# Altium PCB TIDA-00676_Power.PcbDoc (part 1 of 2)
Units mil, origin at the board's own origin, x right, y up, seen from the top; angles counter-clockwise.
Board outline 5000 x 3510 mil, 2 copper layers (Top Layer, Bottom Layer), stack 40 mil thick; 88 components, 29 nets, 205 pads, 45 vias.
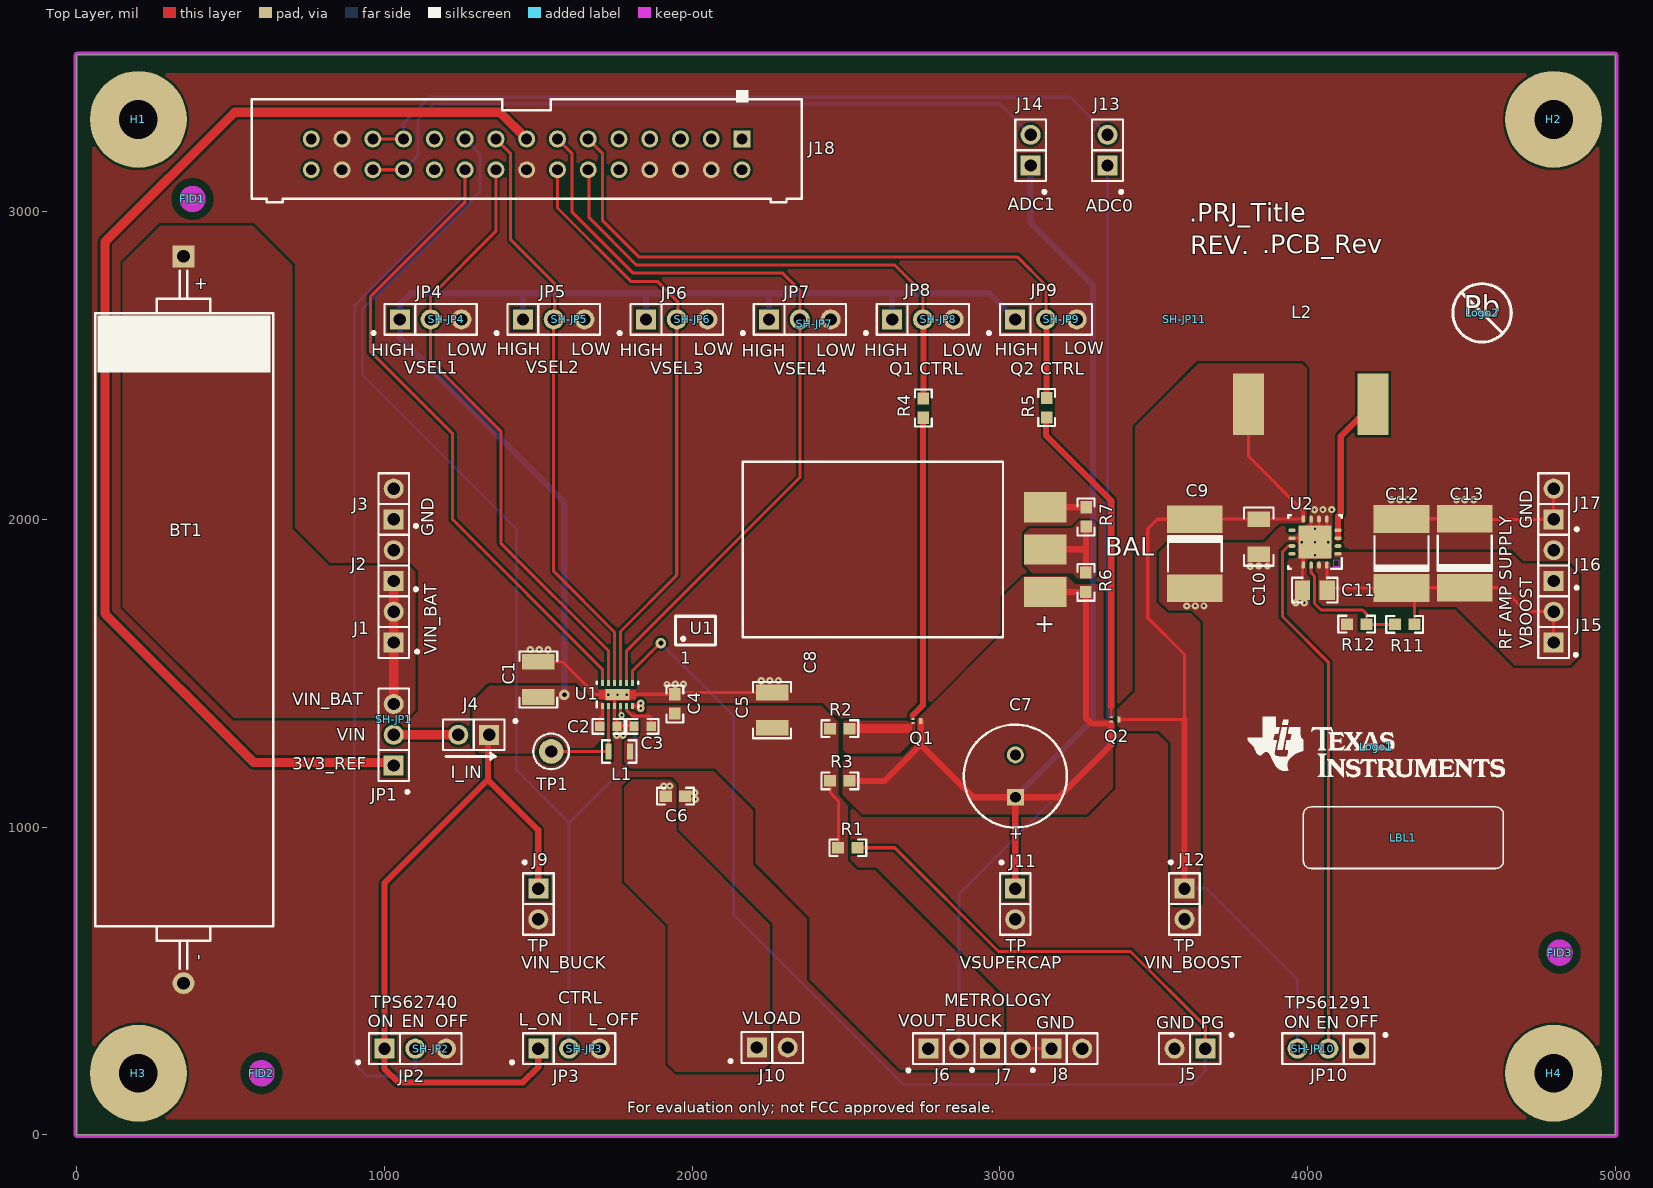
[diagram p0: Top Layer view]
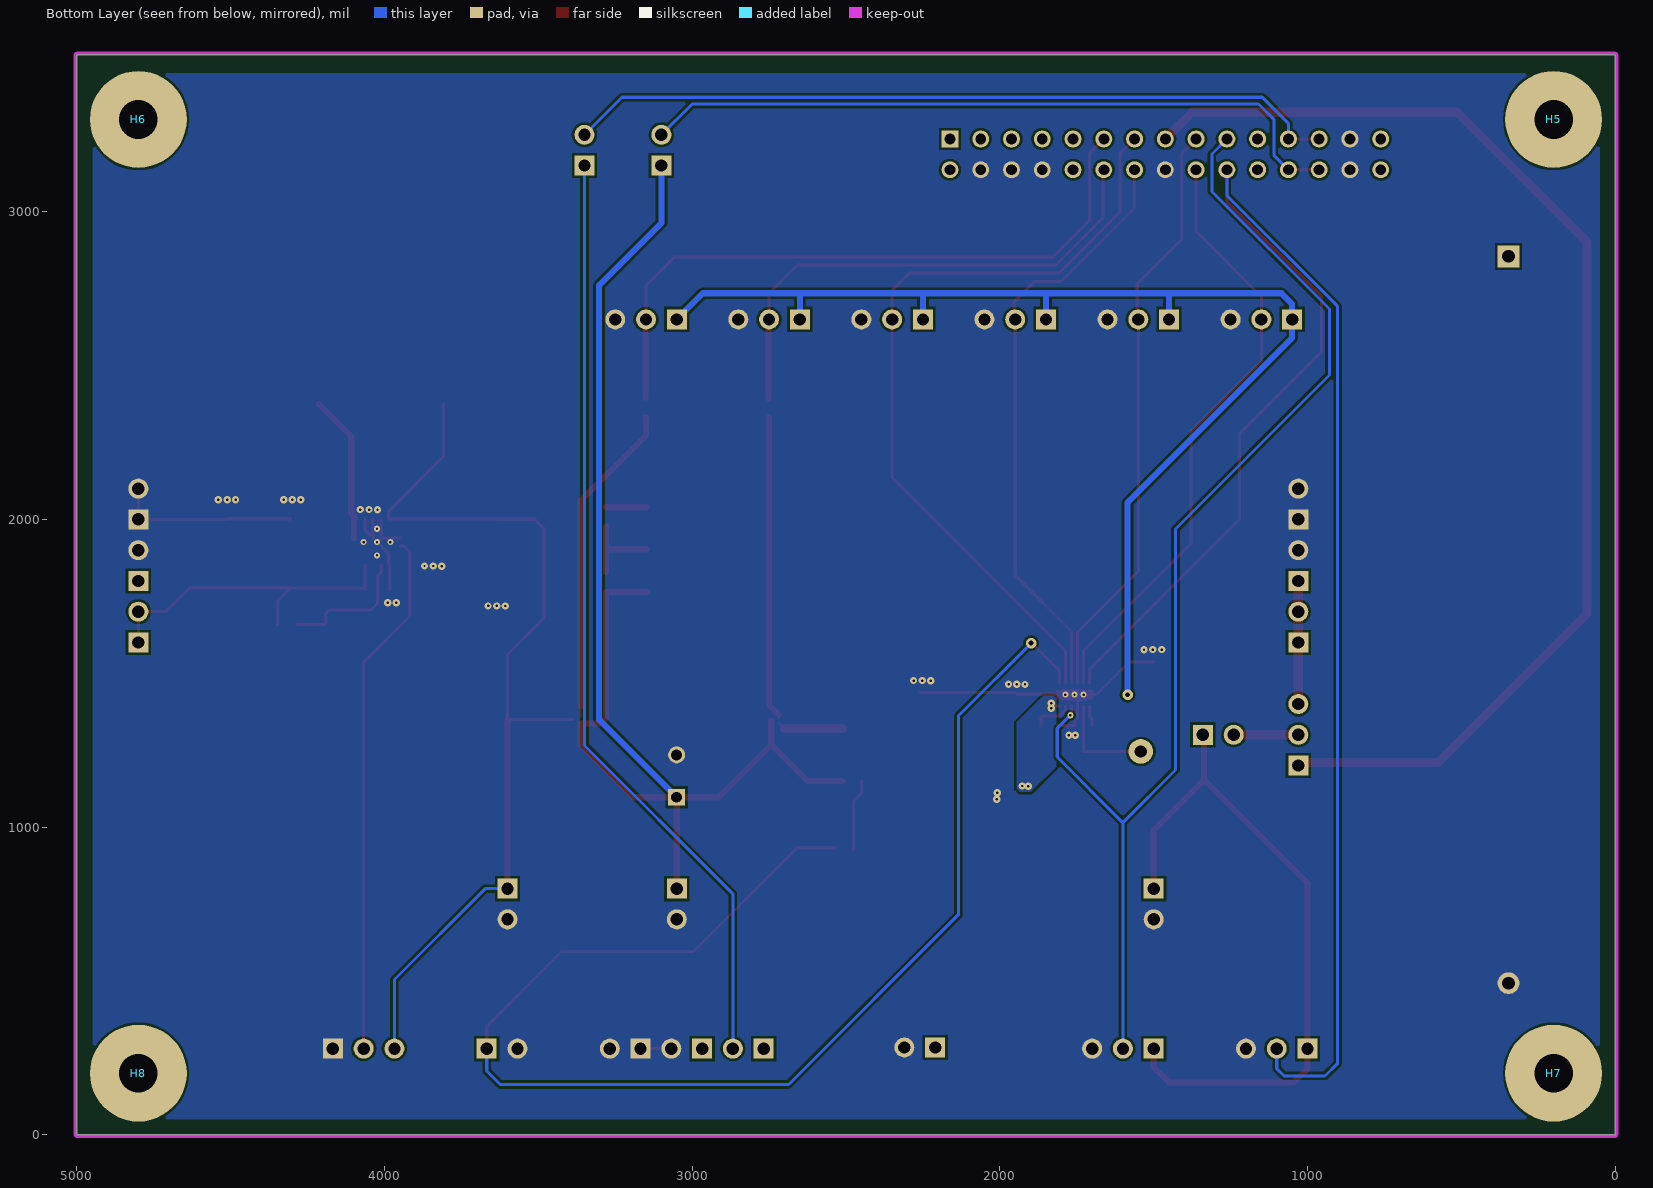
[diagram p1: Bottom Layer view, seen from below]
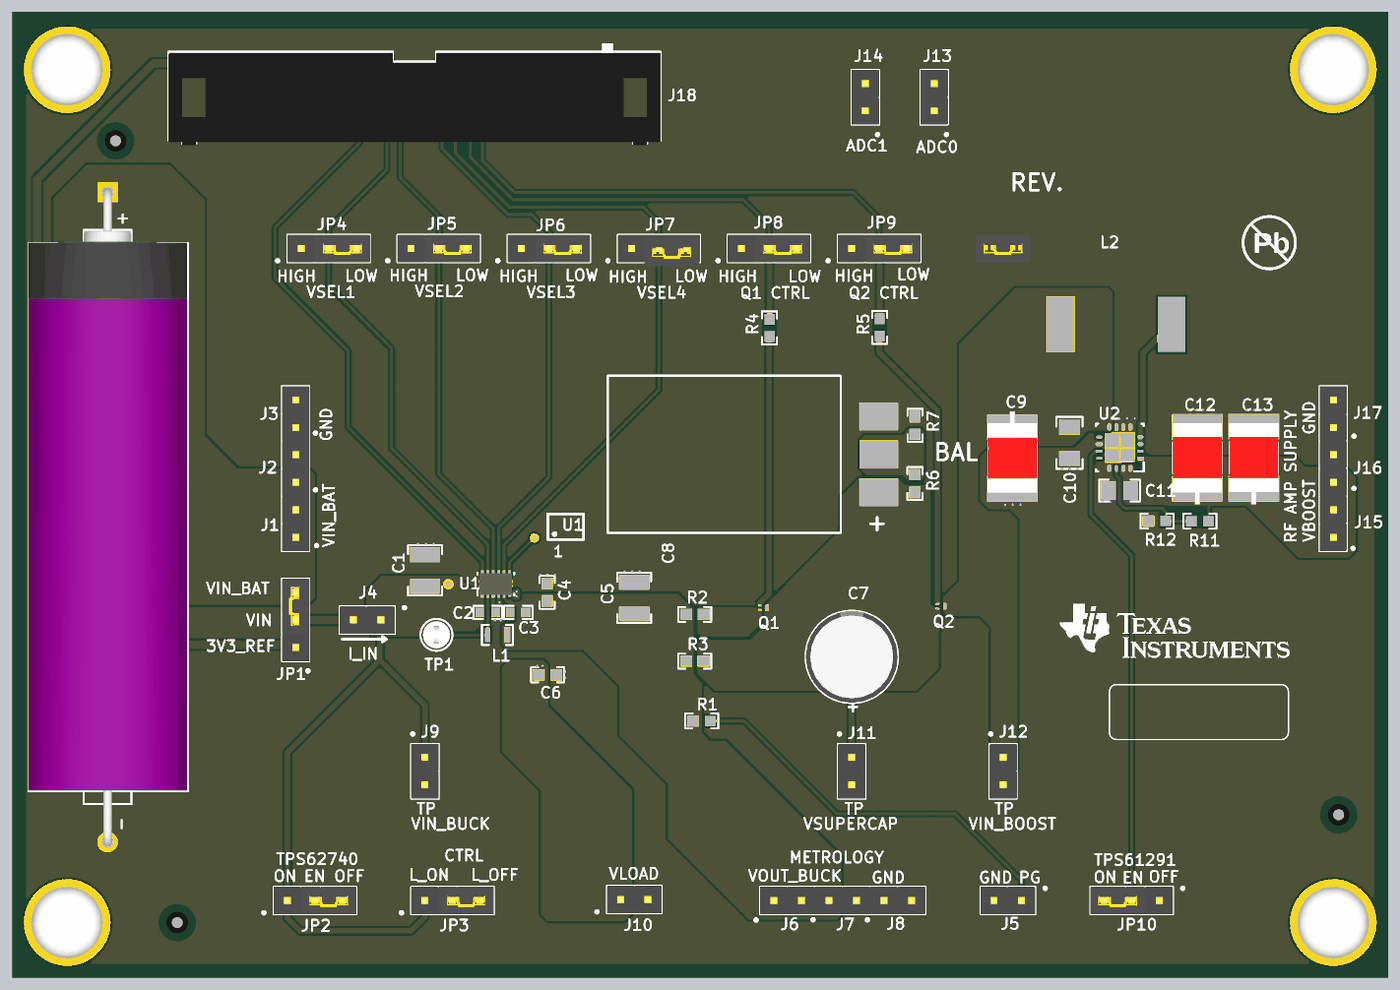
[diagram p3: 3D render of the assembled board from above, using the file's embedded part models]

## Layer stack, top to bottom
Top Solder: solder mask 0.4, Solder Resist, Dk 3.5
Top Layer: signal copper 1.4
Dielectric1: core 37.2, FR-4, Dk 4.8
Bottom Layer: signal copper 1.4
Bottom Solder: solder mask 0.4, Solder Resist, Dk 3.5

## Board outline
0,0 5000,0 5000,3510 0,3510

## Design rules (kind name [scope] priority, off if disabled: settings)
AcuteAngle [All] p1: minimum=4.50000000000000E+0001 checktracksonly=FALSE
AssemblyTestPointUsage [All] p1: valid=2
Clearance Clearance_U2 [InComponent('U2')] p1: gap=7.87
Clearance Clearance_Q1_Q2 [(InNet('NetQ1_2') OR InNet('Q2_CTRL'))] p2: gap=7.4
Clearance Clearance_Keepouts [((IsTrack Or IsArc) And Not InPoly) And IsFree and IsKeepOut vs ((IsTrack Or IsArc) And Not InPoly) And IsFree and IsKeepOut] p3: gap=0
Clearance Clearance_BoardEdge_MountingHoles [OnCopper and InComponentClass('Mounting Holes') vs IsKeepOut] p4: gap=40
Clearance Clearance_BoardEdge_Poly [OnCopper and InPoly vs IsKeepOut] p5: gap=25
Clearance Clearance_BoardEdge [OnCopper and Not InComponentClass('Logo') and not InComponentClass('FiducialMark') and not InRegion(1000,500,4000,800) and Not IsKeepout vs IsKeepOut] p6: gap=36
Clearance Clearance_Poly [InPolygon] p7: gap=7.87
Clearance [All] p8: gap=7.87
ComponentClearance ComponentClearance_1 [(InComponent('J1') OR InComponent('J2') OR InComponent('J3') OR InComponent('J6') OR InComponent('J7') OR InComponent('J8') OR InComponent('J15') OR InComponent('J16') OR InComponent('J17') OR InComponent('SH-JP1') OR InComponent('SH-JP2') OR InComponent('SH-JP3') OR InComponent('SH-JP4') OR InComponent('SH-JP5') OR InComponent('SH-JP6') OR InComponent('SH-JP7') OR InComponent('SH-JP8') OR InComponent('SH-JP9') OR InComponent('SH-JP10') OR InComponent('SH-JP11'))] p1: gap=0 collisioncheckmode=3 verticalgap=0 showdistances=FALSE
ComponentClearance ComponentClearance_Logo [InComponentClass(Logo)] p2: gap=50 collisioncheckmode=3 verticalgap=10 showdistances=FALSE
ComponentClearance ComponentClearance_ScrewToNut [(HasFootprint('NY PMS 440 0025 PH')) vs (HasFootprint('Keystone_1902C'))] p3: gap=5 collisioncheckmode=3 verticalgap=10 showdistances=FALSE
ComponentClearance ComponentClearance_MountingHoles [InComponentClass('Mounting Holes')] p4: gap=50 collisioncheckmode=3 verticalgap=0 showdistances=FALSE
ComponentClearance ComponentClearance_SmallPassives [HasFootprint('0201*') or HasFootprint('0402*') or HasFootprint('0508') or HasFootprint('0603*') or HasFootprint('0612') or HasFootprint('0805*') or HasFootprint('0815*') or HasFootprint('0830*') or HasFootprint('1206*') or HasFootprint('1210*') or HasFootprint('1808*') or HasFootprint('1812*') or HasFootprint('1825*') or HasFootprint('2010*') or HasFootprint('2220*') or HasFootprint('2225*') or HasFootprint('2512*') or HasFootprint('2728*') or HasFootprint('3518*') vs HasFootprint('0201*') or HasFootprint('0402*') or HasFootprint('0508') or HasFootprint('0603*') or HasFootprint('0612') or HasFootprint('0805*') or HasFootprint('0815*') or HasFootprint('0830*') or HasFootprint('1206*') or HasFootprint('1210*') or HasFootprint('1808*') or HasFootprint('1812*') or HasFootprint('1825*') or HasFootprint('2010*') or HasFootprint('2220*') or HasFootprint('2225*') or HasFootprint('2512*') or HasFootprint('2728*') or HasFootprint('3518*')] p5: gap=20 collisioncheckmode=3 verticalgap=10 showdistances=FALSE
ComponentClearance ComponentClearance_THtoSMT [IsThruComponent vs IsSMTComponent] p6: gap=30 collisioncheckmode=3 verticalgap=0 showdistances=FALSE
ComponentClearance ComponentClearance_THtoTH [IsThruComponent vs IsThruComponent] p7: gap=15 collisioncheckmode=3 verticalgap=0 showdistances=FALSE
ComponentClearance [All] p8: gap=20 collisioncheckmode=3 verticalgap=10 showdistances=FALSE
DiffPairsRouting [All] p1: maxlimit=100 minlimit=10 mostfreqgap=10 toplayer_minwidth=15 toplayer_maxwidth=15 toplayer_prefwidth=15 bottomlayer_minwidth=15 bottomlayer_maxwidth=15 bottomlayer_prefwidth=15 maxuncoupledlength=1000
FabricationTestPointUsage TestPointUsage [All] p1: valid=2 allowmultiple=FALSE
FabricationTestpoint Testpoint [All] p1: side=3 testpointundercomponent=TRUE minsize=40 maxsize=100 preferedsize=60 minholesize=0 maxholesize=40 preferedholesize=32 testpointgrid=1 allowsidetop=TRUE allowsidebottom=TRUE usegrid=TRUE gridtolerance=0.01
FanoutControl Fanout_LCC [IsLCC] p1: bgadir=Out bgaviamode=Centered fanoutstyle=Auto fanoutdirection=Alternating viagrid=1 // Fanout_LCC (Default Rule)
FanoutControl Fanout_BGA [IsBGA] p2: bgadir=Out bgaviamode=Centered fanoutstyle=Auto fanoutdirection=Alternating viagrid=1 // Fanout_BGA (Default Rule)
FanoutControl Fanout_Default [All] p4: bgadir=Out bgaviamode=Centered fanoutstyle=Auto fanoutdirection=Alternating viagrid=1 // Fanout_Default (Default Rule)
FanoutControl Fanout_Small [(CompPinCount < 5)] p5: bgadir=Out bgaviamode=Centered fanoutstyle=Auto fanoutdirection=OutThenIn viagrid=1 // Fanout_Small (Default Rule)
HoleSize HoleSize_BGA_Room [WithinRoom('BGA_Room')] p1: absolutevalues=TRUE maxlimit=100 minlimit=3.94 maxpercent=80.000 minpercent=20.000
HoleSize [All] p2: absolutevalues=TRUE maxlimit=251 minlimit=7.5 maxpercent=80.000 minpercent=20.000
HoleToHoleClearance HoleToHoleClearance_BGA_Room [All] p1: gap=8 allowstackedmicrovias=TRUE
HoleToHoleClearance [All] p2: gap=10 allowstackedmicrovias=TRUE
MinimumAnnularRing MinimumAnnularRing_U1_U2 [(ObjectKind = 'Via') And (AsMils(ViaDiameter) = 19.685)] p1: minimumring=5.9
MinimumAnnularRing [All] p2: minimumring=8
MinimumSolderMaskSliver MinimumSolderMaskSliver_Logo [InComponentClass('Logo') vs InComponentClass('Logo')] p1: minsoldermaskwidth=0.7
MinimumSolderMaskSliver [All] p2: minsoldermaskwidth=3
PlaneConnect [All] p1: planeconnectstyle=Relief reliefexpansion=10 reliefentries=4 reliefconductorwidth=10 reliefairgap=10
PolygonConnect PolygonConnect_Jumpers [(ObjectKind = 'Pad') And (Layer = 'MultiLayer') And (HoleDiameter = AsMM(1.016))] p1: connectstyle=Relief reliefconductorwidth=25 reliefentries=4 polygonreliefangle="90 Angle" airgapwidth=10
PolygonConnect [All] p2: connectstyle=Direct reliefconductorwidth=10 reliefentries=4 polygonreliefangle="90 Angle" airgapwidth=10
RoutingVias RoutingVias_BGA_Room [WithinRoom('BGA_Room')] p1: holewidth=28 width=50 viastyle="Through Hole" minholewidth=3.94 minwidth=11.81 maxholewidth=28 maxwidth=50
RoutingVias [All] p2: holewidth=16 width=34 viastyle="Through Hole" minholewidth=7.8 minwidth=19.5 maxholewidth=40 maxwidth=65
SMDToCorner [All] p1: distance=31496
SilkToSilkClearance SilkToSilkClearance__Pb-FreeLogo [(HasFootprint('Pb-Free_Overlay_Medium') OR HasFootprint('Pb-Free_Overlay_Small')) vs (HasFootprint('Pb-Free_Overlay_Medium') OR HasFootprint('Pb-Free_Overlay_Small'))] p1: silktosilkclearance=0
SilkToSilkClearance [All] p2: silktosilkclearance=3
SilkToSolderMaskClearance SilkscreenOverComponentPads [IsPad] p1: minsilkscreentomaskgap=1 clearancetoexposedcopper=TRUE
SolderMaskExpansion [All] p1: expansion=2
UnpouredPolygon [All] p1: allowunpoured=FALSE
Width [All] p1: maxlimit=100 minlimit=6 preferedwidth=10 checkconnectedcopper=TRUE
14 further rules are at their usual default settings.

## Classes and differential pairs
component class Shunt: SH-JP1 SH-JP2 SH-JP3 SH-JP4 SH-JP5 SH-JP6 SH-JP7 SH-JP8 SH-JP9 SH-JP10 SH-JP11
component class "Mounting Holes": H1 H2 H3 H4
component class Header: J1 J2 J3 J4 J5 J6 J7 J8 J9 J10 J11 J12 J13 J14 J15 J16 J17 JP1 JP2 JP3 JP4 JP5 JP6 JP7 JP8 JP9 JP10
component class Logo: Logo1
component class FiducialMark: FID1 FID2 FID3
component class AssemblyNote: ZZ1 ZZ2 ZZ3 ZZ4
component class Label: LBL1
component class TIDA-00676_Power_BOOST: C9 C10 C11 C12 C13 J15 J16 J17 JP10 L2 R11 R12 U2
component class TIDA-00676_Power_BUCK: BT1 C1 C2 C3 C4 C5 C6 C7 C8 J1 J2 J3 J4 J5 J6 J7 J8 J9 J10 J11 J12 J13 J14 J18 JP1 JP2 JP3 JP4 JP5 JP6 JP7 JP8 JP9 L1 Q1 Q2 R1 R2 R3 R4 R5 R6 R7 TP1 U1
component class TIDA-00676_Power_Hardware: !PCB FID1 FID2 FID3 H1 H2 H3 H4 H5 H6 H7 H8 LBL1 Logo1 Logo2 Logo3 SH-JP1 SH-JP2 SH-JP3 SH-JP4 SH-JP5 SH-JP6 SH-JP7 SH-JP8 SH-JP9 SH-JP10 SH-JP11 ZZ1 ZZ2 ZZ3 ZZ4

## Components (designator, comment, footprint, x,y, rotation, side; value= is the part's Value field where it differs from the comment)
BT1 "SL360/P" Tadiran_SL360-P 346.8,1673.8 r270 top
C1 "GRM32ER60J107ME20L" 1210 1500,1480 r90 top
C2 "GRM188R60J106ME84" 0603_HV 1727.84,1327.5 r0 top
C3 "GRM188R60J106ME84" 0603_HV 1838.67,1327.5 r180 top
C4 "GRM188R60J106ME84" 0603 1943.87,1400.1 r90 top
C5 "GRM32ER60J107ME20L" 1210 2260,1380 r90 top
C6 "GRM188R60J106ME84" 0603 1945.55,1100.36 r0 top
C7 "ESHSR-0003C0-002R7" ESHSR_800x2000 3050.43,1165.78 r90 top
C8 "DMF3Z5R5H474M3DTA0" DMF_2100x1400 2587.09,1902.1 r180 top
C9 "594D107X0016D2T" CC_CASED 3633.89,1888.36 r270 top
C10 "C3216X5R0J106M" 1206 3841.31,1943.76 r270 top
C11 "08055A2R2CAT2A" 0805_HV 4023.64,1770.26 r180 top
C12 "594D107X0016D2T" CC_CASED 4305.78,1889.47 r90 top
C13 "594D107X0016D2T" CC_CASED 4511.08,1890.04 r90 top
FID1 "Fiducial" Fiducial10-20 375.9,3041.5 r0 top
FID2 "Fiducial" Fiducial10-20 600,200 r0 top
FID3 "Fiducial" Fiducial10-20 4819.42,591.83 r0 top
H1 "NY PMS 440 0025 PH" "NY PMS 440 0025 PH" 200,3300 r0 top locked
H2 "NY PMS 440 0025 PH" "NY PMS 440 0025 PH" 4800,3300 r0 top locked
H3 "NY PMS 440 0025 PH" "NY PMS 440 0025 PH" 200,200 r0 top locked
H4 "NY PMS 440 0025 PH" "NY PMS 440 0025 PH" 4800,200 r0 top locked
H5 "1902C" Keystone_1902C 200,3300 r180 bottom locked
H6 "1902C" Keystone_1902C 4800,3300 r180 bottom locked
H7 "1902C" Keystone_1902C 200,200 r180 bottom locked
H8 "1902C" Keystone_1902C 4800,200 r180 bottom locked
J1 "TSW-102-07-G-S" TSW-102-07-G-S 1030,1650 r90 top
J2 "TSW-102-07-G-S" TSW-102-07-G-S 1030,1850 r90 top
J3 "TSW-102-07-G-S" TSW-102-07-G-S 1030,2050 r90 top
J4 "TSW-102-07-G-S" TSW-102-07-G-S 1290,1300 r180 top
J5 "TSW-102-07-G-S" TSW-102-07-G-S 3617.7,280 r180 top
J6 "TSW-102-07-G-S" TSW-102-07-G-S 2817.7,280 r0 top
J7 "TSW-102-07-G-S" TSW-102-07-G-S 3017.7,280 r0 top
J8 "TSW-102-07-G-S" TSW-102-07-G-S 3217.7,280 r0 top
J9 "TSW-102-07-G-S" TSW-102-07-G-S 1500,750 r270 top
J10 "TSW-102-07-G-S" TSW-102-07-G-S 2260.4,283.7 r0 top
J11 "TSW-102-07-G-S" TSW-102-07-G-S 3050,750 r270 top
J12 "TSW-102-07-G-S" TSW-102-07-G-S 3600,750 r270 top
J13 "TSW-102-07-G-S" TSW-102-07-G-S 3350,3200 r90 top
J14 "TSW-102-07-G-S" TSW-102-07-G-S 3100,3200 r90 top
J15 "TSW-102-07-G-S" TSW-102-07-G-S 4800,1650 r90 top
J16 "TSW-102-07-G-S" TSW-102-07-G-S 4800,1850 r90 top
J17 "TSW-102-07-G-S" TSW-102-07-G-S 4800,2050 r90 top
J18 "XG4C-3031" OMRON_XG4C-3031 1462.1,3204.1 r180 top
JP1 "TSW-103-07-G-S" TSW-103-07-G-S#1 1030,1300 r90 top
JP2 "TSW-103-07-G-S" TSW-103-07-G-S#2 1100,280 r0 top
JP3 "TSW-103-07-G-S" TSW-103-07-G-S#1 1600,280 r0 top
JP4 "TSW-103-07-G-S" TSW-103-07-G-S#1 1150,2650 r0 top
JP5 "TSW-103-07-G-S" TSW-103-07-G-S#1 1550,2650 r0 top
JP6 "TSW-103-07-G-S" TSW-103-07-G-S#1 1950,2650 r0 top
JP7 "TSW-103-07-G-S" TSW-103-07-G-S#1 2350,2650 r0 top
JP8 "TSW-103-07-G-S" TSW-103-07-G-S#1 2750,2650 r0 top
JP9 "TSW-103-07-G-S" TSW-103-07-G-S#1 3150,2650 r0 top
JP10 "TSW-103-07-G-S" TSW-103-07-G-S#2 4067.7,280 r180 top
L1 "MIPSZ20120D2R2" MIPSZ20120D 1763.07,1245.5 r0 top
L2 "CDRH124-6R8" IND_CDRH124 2280.62,2374.34 r0 top
LBL1 "Size: 0.65\" x 0.20 \"" Label_650x200 4311.71,965.33 r180 top
Logo1 "Texas Instruments" TI_Stacked_Overlay_Small 4223.44,1260.41 r0 top
Logo2 "Pb-Free Symbol" Pb-Free_Overlay_Medium 4567.23,2671.32 r0 top
Logo3 "FCC disclaimer" FCC_disclaimer 5331.11,692.09 r90 top
Q1 "CSD23381F4" YJC0003A 2730,1345 r270 top
Q2 "CSD23381F4" YJC0003A 3375,1350 r270 top
R1 "RC0603FR-071ML" 0603 2505.8,932.7 r180 top
R2 "CRCW060330R0JNEA" 0603 2480,1320 r0 top
R3 "RC0603FR-07300RL" 0603 2480,1150 r0 top
R4 "CRCW06032K70JNEA" 0603 2751.67,2361.81 r270 top
R5 "CRCW06032K70JNEA" 0603 3151.92,2363.29 r270 top
R6 "Used in BOM report" 0603 3279.85,1795.57 r270 top
R7 "Used in BOM report" 0603 3280.1,2007.89 r270 top
R11 "CRCW06031M10FKEA" 0603 4315.76,1658.86 r0 top
R12 "CRCW0603180KJNEA" 0603 4159.8,1659.45 r0 top
SH-JP1 "969102-0000-DA" SNT-100-BK-G 1030,1350 r90 top
SH-JP2 "969102-0000-DA" SNT-100-BK-G 1150,280 r180 top
SH-JP3 "969102-0000-DA" SNT-100-BK-G 1650,280 r180 top
SH-JP4 "969102-0000-DA" SNT-100-BK-G 1200,2650 r180 top
SH-JP5 "969102-0000-DA" SNT-100-BK-G 1600,2650 r180 top
SH-JP6 "969102-0000-DA" SNT-100-BK-G 2000,2650 r180 top
SH-JP7 "969102-0000-DA" SNT-100-BK-G 2396.15,2636.5 r180 top
SH-JP8 "969102-0000-DA" SNT-100-BK-G 2800,2650 r180 top
SH-JP9 "969102-0000-DA" SNT-100-BK-G 3200,2650 r180 top
SH-JP10 "969102-0000-DA" SNT-100-BK-G 4016.7,280 r180 top
SH-JP11 "969102-0000-DA" SNT-100-BK-G 3600,2650 r180 top
TP1 "5002" Keystone5002 1541.67,1245.8 r0 top
U1 "TPS62740DSS" DSS0012A 1757.37,1430.4 r90 top locked
U2 "TPS61030RSAR" RSA0016B 4024.43,1926.3 r180 top
ZZ1 "This Assembly Note is for PCB labels only" AssemblyNoteLabel 254.68,4101.89 r0 top
ZZ2 "These assemblies are ESD sensitive, ESD precautions shall be observed." AssemblyNote 254.68,3993.01 r0 top
ZZ3 "These assemblies must be clean and free from flux and all contaminants. Use of no clean flux is not acceptable." AssemblyNote 254.68,3904.45 r0 top
ZZ4 "These assemblies must comply with workmanship standards IPC-A-610 Class 2., unless otherwise specified." AssemblyNote 254.68,3815.89 r0 top

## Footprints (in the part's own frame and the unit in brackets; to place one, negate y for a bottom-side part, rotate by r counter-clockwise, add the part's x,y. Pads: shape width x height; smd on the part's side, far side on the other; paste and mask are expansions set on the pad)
0603 [mm] "0603 from SM-752 data"
  rect 1x0.95 smd: 1(-0.8,0) 2(0.8,0)
  silkscreen extent -1.52,-0.69 1.52,0.69, body extent -0.87,-0.47 0.87,0.47, height 0.85
0603_HV [mil] "Ernesto recommended land pattern.  26 mil between pads."
  rect 30x30 smd: 1(-28,0) 2(28,0)
  silkscreen extent -52,-24 52,24, body extent -34,-19 34,19, height 33
0805_HV [mil] "0805 with 30mil clearance between pads"
  rect 50x63 smd: 1(-40,0) 2(40,0)
  silkscreen extent -74,-40 74,40, body extent -43,-29 43,29, height 43
1206 [mm] "1206 from SM-752 data"
  rect 1.3x1.85 smd: 1(-1.45,0) 2(1.45,0)
  silkscreen extent -2.4,-1.21 2.4,1.21, body extent -1.7,-0.9 1.7,0.9, height 1.35
1210 [mm] "1210 from SM-752 data"
  rect 1.3x2.7 smd: 1(-1.45,0) 2(1.45,0)
  silkscreen extent -2.32,-1.57 2.32,1.57, body extent -1.7,-1.35 1.7,1.35, height 1.35
AssemblyNote [mil] "Assembly Note"
AssemblyNoteLabel [mil] "Assembly Note for PCB Labels"
CC_CASED [mm] "Vishay recommended land pattern"
  rect 2.3x4.6 smd: 1(-2.85,0) 2(2.85,0)
  silkscreen extent -1.45,-2.23 1.45,2.22, body extent -4.3,-2.3 3.2,2.3, height 3.1
DMF_2100x1400 [mm] "Electrical  Double Layer Capacitor, Body 21.5x14.5mm, Pitch 3.5mm"
  rect 3.5x2.5 smd: 1(-14.25,3.5) 2(-14.25,-3.5) 3(-14.25,0)
  silkscreen extent -10.75,-7.25 10.75,7.25, body extent -14.75,-7.25 10.75,7.25, height 3.2
DSS0012A [mm] "SON, 12-Leads, Body 2x3mm, Pitch 0.5mm, Thermal Pad 2x0.9mm, TI Recommended"
  rect 0.5x0.25 smd: 1(-0.95,1.25) 2(-0.95,0.75) 3(-0.95,0.25) 4(-0.95,-0.25) 5(-0.95,-0.75) 6(-0.95,-1.25) 7(0.95,-1.25) 8(0.95,-0.75) 9(0.95,-0.25) 10(0.95,0.25) 11(0.95,0.75) 12(0.95,1.25)
  rect 0.9x2 smd paste-0.45: 13(0,0)
  Top Layer region: -0.375,-1.5 -0.375,-1 -0.45,-1 -0.45,1 -0.375,1 -0.375,1.5 -0.125,1.5 -0.125,1 0.125,1 0.125,1.5 0.375,1.5 0.375,1 0.45,1 0.45,-1 0.375,-1 0.375,-1.5 0.125,-1.5 0.125,-1 -0.125,-1 -0.125,-1.5
  silkscreen extent -1.05,-1.7 1.05,1.7, body extent -1,-1.5 1,1.5, height 0.81
ESHSR_800x2000 [mm] "TH, 2-Leads, 8mm Dia"
  rect 1.4x1.4 hole 0.9: 1(-1.75,0)
  round 1.4 hole 0.9: 2(1.75,0)
  silkscreen extent -4.25,-4.25 4.25,4.25, body extent -4.22,-4.24 4.24,4.24, height 22.01
FCC_disclaimer [mil]
Fiducial10-20 [mm]
  round 1 smd mask+0.5: 1(0,0)
  Top Layer keep-out circle w1.178: c0,0 r0.5
IND_CDRH124 [mil]
  rect 100x200 smd: 1(1527.94,0) 2(1931.94,0)
Keystone5002 [mil] "For Keystone 500x miniature loop terminals"
  round 80 hole 40: 1(0,0)
  silkscreen extent -58,-58 58,58, body extent -49,-49 49,49, height 182
Keystone_1902C [mil] "Hex Standoff, 4-40 threaded, nylon"
  round 1 on Mech4: 0(0,0)
  body extent -145,-126 146,126, height 501
Label_650x200 [mil] "Thermal Transfer Label"
  round 1 on Mech13: 0(0,0)
  silkscreen extent -325,-100 325,100, body extent -326,-101 326,101, height 1
MIPSZ20120D [mm] "0805 from FDK data"
  rect 0.5x1.3 smd: 1(-0.9,0) 2(0.9,0)
  silkscreen extent -1.43,-0.92 1.43,0.92, body extent -1.1,-0.72 1.1,0.72, height 1
"NY PMS 440 0025 PH" [mm] "4-40 nylon screw and mounting hole"
  round 8 hole 3.2: 1(0,0)
  body extent -3.3,-3.3 3.3,3.3, height 2.69
OMRON_XG4C-3031 [mm] "Connector, 15x2, 3A 300V STRT DIP, TH"
  rect 1.4x1.4 hole 0.9: 1(-17.78,-0.82)
  round 1.4 hole 0.9: 2(-17.78,1.72) 3(-15.24,-0.82) 4(-15.24,1.72) 5(-12.7,-0.82) 6(-12.7,1.72) 7(-10.16,-0.82) 8(-10.16,1.72) 9(-7.62,-0.82) 10(-7.62,1.72) 11(-5.08,-0.82) 12(-5.08,1.72) 13(-2.54,-0.82) 14(-2.54,1.72) 15(0,-0.82) 16(0,1.72) 17(2.54,-0.82) 18(2.54,1.72) 19(5.08,-0.82) 20(5.08,1.72) 21(7.62,-0.82) 22(7.62,1.72) 23(10.16,-0.82) 24(10.16,1.72) 25(12.7,-0.82) 26(12.7,1.72) 27(15.24,-0.82) 28(15.24,1.72) 29(17.78,-0.82) 30(17.78,1.72)
  silkscreen extent -22.7,-4.86 22.7,4.4, body extent -22.7,-3.95 22.7,4.55, height 8.5
Pb-Free_Overlay_Medium [mil]
  silkscreen extent -95,-95 95,95
RSA0016B [mm] "QFN, 16-Leads, Body 4x4mm, Pitch 0.65mm, Thermal Pad 2.7x2.7mm, TI Recommended"
  oval 0.6x0.3 smd: 1(-1.9,0.975) 2(-1.9,0.325) 3(-1.9,-0.325) 4(-1.9,-0.975) 9(1.9,-0.975) 10(1.9,-0.325) 11(1.9,0.325) 12(1.9,0.975)
  oval 0.3x0.6 smd: 5(-0.975,-1.9) 6(-0.325,-1.9) 7(0.325,-1.9) 8(0.975,-1.9) 13(0.975,1.9) 14(0.325,1.9) 15(-0.325,1.9) 16(-0.975,1.9)
  rect 2.7x2.7 smd paste-1.35: 17(0,0)
  Top Layer keep-out region: -2,1.5 -1.5,1.5 -1.5,2 -2,2
  silkscreen extent -2.2,-2.2 2.2,2.2, body extent -2.05,-2.05 2.05,2.05, height 1.01
SNT-100-BK-G [mil] "Samtec STEP model"
  round 1 on Mech3: 0(0,0)
  body extent -100,-50 100,50, height 344
Tadiran_SL360-P [mm] "Battery"
  rect 1.8x1.8 hole 1.05: 1(-30,0)
  round 1.8 hole 1.05: 2(30,0)
  silkscreen extent -28.8,-7.3 28.8,7.4, body extent -30.4,-7.35 30.4,7.36, height 14.7
TI_Stacked_Overlay_Small [mil]
  silkscreen extent -418,-98 418,98
TSW-102-07-G-S [mm] "Samtec 100mil, 1x2, 230 mil above insulator"
  rect 1.65x1.65 hole 1.016 mask+0: 1(-1.27,0)
  round 1.65 hole 1.016 mask+0: 2(1.27,0)
  silkscreen extent -2.54,-2.06 2.54,1.27, body extent -2.54,-1.27 2.54,1.27, height 8.38
TSW-103-07-G-S#1 [mm] "Samtec 100mil, 1x3, 230 mil above insulator"
  rect 1.65x1.65 hole 1.016 mask+0: 1(-2.54,0)
  round 1.65 hole 1.016 mask+0: 2(0,0) 3(2.54,0)
  silkscreen extent -4.83,-1.27 3.81,1.27, body extent -3.81,-1.27 3.81,1.27, height 8.38
TSW-103-07-G-S#2 [mm] "Samtec 100mil, 1x3, 230 mil above insulator"
  rect 1.65x1.65 hole 1.016: 1(-2.54,0)
  round 1.65 hole 1.016: 2(0,0) 3(2.54,0)
  silkscreen extent -4.83,-1.27 3.81,1.27, body extent -3.81,-1.27 3.81,1.27, height 8.38
YJC0003A [mm] "TI"
  rect 0.16x0.26 smd: 1(-0.175,-0.325) 2(0.175,-0.325)
  rect 0.51x0.26 smd: 3(0,0.325)
  body extent -0.32,-0.52 0.32,0.52, height 0.35

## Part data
BT1: "Battery, 3.6 V, 2.4 Ah, Axial, TH"
C1 C5: "CAP, CERM, 100uF, 6.3V, +/-20%, X5R, 1210"
C2 C3 C4 C6: "CAP, CERM, 10uF, 6.3V, +/-20%, X5R, 0603"
C7: "CAP, Electric Double Layer, 3000000uF, 2.7V, +20/-10%, 0.061 ohm, TH"
C8: "CAP, Electric Double Layer, 470000uF, 4.2 V, +/- 20%, 0.045 ohm, Electrical  Double Layer Capacitor, Body 21.5x14.5mm, Pitch 3.5mm SMD"
C9 C12 C13: "CAP, TA, 100 µF, 16 V, +/- 20%, 0.09 ohm, SMD"
C10: "CAP, CERM, 10 µF, 6.3 V, +/- 20%, X5R, 1206"
C11: "CAP, CERM, 2.2 pF, 50 V, +/- 11%, C0G/NP0, 0805"
FID1 FID2 FID3: "Fiducial mark.  There is nothing to buy or mount."
H1 H2 H3 H4: "Machine Screw, Round, #4-40 x 1/4, Nylon, Philips panhead"
H5 H6 H7 H8: "Standoff, Hex, 0.5\"L #4-40 Nylon"
J1 J2 J3 J4 J5 J6 J7 J8 J9 J10 J11 J12 J13 J14 J15 J16 J17: "Header, TH, 100mil, 2x1, Gold plated, 230 mil above insulator"
J18: "Connector, 15x2, 3A 300V STRT DIP, TH"
JP1 JP2 JP3 JP4 JP5 JP6 JP7 JP8 JP9 JP10: "Header, TH, 100mil, 3x1, Gold plated, 230 mil above insulator"
L1: "Inductor, Multilayer, Ceramic, 2.2uH, 0.7A, 0.23 ohm, SMD"
L2: library part IND_CDRH124_SERIES, "Inductor, SMT, yyA, zzmilliohm"
LBL1: library part THT-14-423-10, "Thermal Transfer Printable Labels, 0.650\" W x 0.200\" H - 10,000 per roll"
Logo1: library part TI_Logo, "Texas Instrument Corporate Signature"
Logo2: library part Pb-Free
Logo3: library part FCC_disclaimer, "FCC_disclaimer"
Q1 Q2: "MOSFET, P-CH, -12V, -2.3A, 1.0x0.35x0.6mm"
R1: "RES, 1.00Meg ohm, 1%, 0.1W, 0603"
R2: "RES, 30 ohm, 5%, 0.1W, 0603"
R3: "RES, 300 ohm, 1%, 0.1W, 0603"
R4 R5: "RES, 2.7k ohm, 5%, 0.1W, 0603"
R6 R7: library part Resistor, "RES, xxx ohm, x%, xW, [PackageReference]"
R11: "RES, 1.10 M, 1%, 0.1 W, 0603"
R12: "RES, 180 k, 5%, 0.1 W, 0603"
SH-JP1 SH-JP2 SH-JP3 SH-JP4 SH-JP5 SH-JP6 SH-JP7 SH-JP8 SH-JP9 SH-JP10 SH-JP11: "Shunt, 100mil, Gold plated, Black"
TP1: "Test Point, Miniature, White, TH"
U1: "360nA IQ Step Down Converter for Low Power Applications, DSS0012A"
U2: "96% Efficient Synchronous Boost Converter With 4A Switch, RSA0016B"
ZZ1: library part AssemblyNoteLabel
ZZ2 ZZ3 ZZ4: library part AssemblyNote

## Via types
v1: diameter 24, hole 8, Top Layer to Bottom Layer, tented both sides, 34 vias
v2: diameter 19.68, hole 7.87, Top Layer to Bottom Layer, 5 vias
v3: diameter 19.68, hole 7.87, Top Layer to Bottom Layer, tented both sides, 4 vias
v4: diameter 34, hole 16, Top Layer to Bottom Layer, 2 vias

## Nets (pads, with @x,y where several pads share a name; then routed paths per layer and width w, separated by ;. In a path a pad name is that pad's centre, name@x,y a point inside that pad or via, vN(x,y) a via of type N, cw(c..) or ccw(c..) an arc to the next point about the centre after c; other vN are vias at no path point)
3V3_REF: J18.15 JP1.1 | length 3928.8
  Top Layer w30: JP1.1@1030,1210 575,1210 91.26,1693.74 91.26,2901.71 513.14,3323.6 1374.88,3323.6 J18.15@1462.1,3236.38
ADC0: J13.2 J18.23 J18.25 | length 2524.3
  Top Layer w10: J18.25@962.1,3236.38 J18.23@1062.1,3236.38
  Bottom Layer w10: J18.23@1062.1,3236.38 1062.1,3287.1 1147.02,3372.02 3227.98,3372.02 J13.2@3350,3250
ADC1: J14.2 J18.24 J18.26 | length 2336
  Top Layer w10: J18.26@962.1,3136.38 J18.24@1062.1,3136.38
  Bottom Layer w10: J18.24@1062.1,3136.38 1109.53,3183.82 1109.53,3300.17 1159.36,3350 3000,3350 J14.2@3100,3250
BOOST_EN/BYP: JP10.2 U2.11 | length 1715
  Top Layer w10: U2.11@3949.63,1913.51 3937.34,1913.51 3918.96,1895.13 3918.96,1684.17 4067.7,1535.43 JP10.2@4067.7,280
CTRL: J18.19 JP3.2 U1.4 | length 3898.8
  Top Layer w10: U1.4@1767.21,1393 1767.21,1367.36 1771.07,1363.5 v3(1770.97,1363.4)
  Bottom Layer w10: J18.19@1262.1,3236.38 1310.59,3187.9 1310.59,3065.42 928.74,2683.57 928.74,2469.3 1429.13,1968.91 1429.13,1185.23 1600,1014.36 ; JP3.2@1600,280 1600,1014.36 ; v3(1770.97,1363.4) 1813.3,1321.07 1813.3,1227.67 1600,1014.36
EN: J18.20 JP2.2 U1.12 | length 5451
  Top Layer w10: J18.20@1262.1,3136.38 1262.1,3032.1 955,2725 955,2545 1221.51,2278.49 1221.51,1999.73 1708.16,1513.08 U1.12@1708.16,1467.8
  Bottom Layer w10: JP2.2@1100,280 1100,215 1076.11,191.11 943.21,191.11 901.94,232.38 901.94,2692.38 1262.1,3052.54 J18.20@1262.1,3136.38
GND: BT1.2 C1.2 C2.2 C3.2 C4.2 C5.2 C6.2 C7.2 C8.2 C9.2 C10.2 C11.2 C12.2 C13.2 J2.2 J3.1 J3.2 J5.2 J7.2 J8.1 J8.2 J9.2 J10.2 J11.2 J12.2 J16.2 J17.1 J17.2 J18.4 J18.6 J18.8 J18.16 J18.27 J18.28 JP2.3 JP3.3 JP4.3 JP5.3 JP6.3 JP7.3 JP8.3 JP9.3 JP10.1 R7.1 R12.1 U1.3 U1.13 U2.5 U2.6 U2.7 U2.10 U2.13 U2.17 | length 2256.3
  Top Layer w10: J3.1@1030,1978.3 J3.1@1030,2000 ; C1.2@1500,1537.09 1578.31,1537.09 1684.62,1430.77 1727.48,1430.77 v3(1727.84,1430.4) ; C3.2@1810.47,1330.8 1755.87,1330.8 1755.77,1330.9 1755.77,1346.48 1748.26,1353.99 1748.26,1354.11 1747.53,1354.83 U1.3@1747.53,1393 1747.53,1420.56 v3(1757.37,1430.4) 1757.51,1430.27 1824.58,1430.27 1825.91,1431.6 C4.2@1943.87,1431.6 1949.36,1437.09 C5.2@2260,1437.09 ; J7.2@3067.7,280 J8.1@3167.7,280 ; C8.2@3148.12,2039.89 C8.2@3148.62,2039.39 ; U2.10@3949.63,1939.1 U2.17@4011.64,1939.1 ; C11.2@3983.64,1770.26 3983.64,1849.1 U2.13@3986.05,1851.5 3986.05,1887.92 v2(4024.43,1926.3) ; U2.7@4011.64,2001.11 U2.17@4011.64,1939.1 ; U2.6@4037.23,2001.11 U2.17@4037.23,1939.1 ; U2.5@4062.82,2001.11 4062.82,1964.69 U2.17@4037.23,1939.1 ; C12.2@4305.78,2001.68 4306.34,2002.24 C13.2@4511.08,2002.24 4513.32,2000 J17.1@4800,2000 J17.2@4800,2100 ; U2.17@4011.64,1939.1 v2(4024.43,1926.3) ; v2(4024.43,1926.3) U2.17@4037.23,1939.1
  Top Layer w20: C8.2@3148.62,2039.39 R7.1@3280.1,2039.39
  other v1: 2010,1090.48 2008.96,1111.48 1754.5,1298.93 1775.39,1298.69 1918.2,1463.5 1945.21,1463.94 1971.77,1463.72 2224.91,1476 2252.37,1476.22 2280.49,1476.22 1473.82,1577.05 1503.2,1577.05 1531.38,1576.85 3607.87,1718.5 3635.32,1718.73 3663.45,1718.73 3962.09,1729.3 3989.55,1729.52 3814.34,1848.33 3841.8,1848.55 3869.92,1848.55 4022.76,2031.9 4050.22,2032.12 4078.35,2032.12 4271.91,2063.27 4299.37,2063.49 4327.5,2063.49 4484.14,2063.27 4511.59,2063.49 4539.72,2063.49
  other v2: 4024.43,1883 3981.12,1926.3 4067.74,1926.3 4024.43,1969.61
  other v3: 1786.9,1430.4
GPIO6: J18.12 JP8.2 R4.1 | length 1686.5
  Top Layer w10: J18.12@1662.1,3136.38 1665,3133.48 1665,2980 1817.67,2827.33 2657.67,2827.33 2750,2735 JP8.2@2750,2650 JP8.2@2751.67,2648.33
  Top Layer w20: R4.1@2751.67,2393.3 JP8.2@2751.67,2648.33
GPIO7: J18.11 JP9.2 R5.1 | length 2179.2
  Top Layer w10: J18.11@1662.1,3236.38 1708.1,3190.38 1708.1,2971.9 1826.52,2853.48 3056.52,2853.48 3150,2760 JP9.2@3150,2650 JP9.2@3151.92,2648.08
  Top Layer w20: R5.1@3151.92,2394.79 JP9.2@3151.92,2648.08
NetC8_3: C8.3 R6.1 R7.2 | length 281.6
  Top Layer w20: C8.3@3148.12,1902.1 3149.07,1903.05 3279.85,1903.05 ; R6.1@3279.85,1827.07 3279.85,1903.05 ; R7.2@3280.1,1976.4 3279.85,1976.15 3279.85,1903.05
NetJ4_2: J4.2 JP1.2 | length 214.1
  Top Layer w30: JP1.2@1030,1310 1040,1300 J4.2@1240,1300
NetJ5_1: J5.1 R1.1 U1.7 | length 4447.6
  Top Layer w10: U1.7@1806.59,1467.8 1806.59,1508.65 v4@1898.09,1600.15 ; R1.1@2537.3,932.7 2658.54,932.7 2995.65,595.6 3424.7,595.6 3667.7,352.59 J5.1@3667.7,280 J5.1@3668.4,280.7
  Bottom Layer w10: v4(1898.09,1597.94) 2135,1361.03 2135,715 2686.57,163.43 3623.77,163.43 3667.7,207.36 J5.1@3667.7,280
NetL1_1: L1.1 TP1.1 U1.2 | length 336.9
  Top Layer w10: TP1.1@1541.67,1245.8 1541.97,1245.5 L1.1@1727.64,1245.5 1730.07,1245.5 1727.84,1247.73 U1.2@1727.84,1393
NetL2_2: L2.2 U2.3 U2.4 | length 482.2
  Top Layer w20: U2.3@4099.23,1939.1 U2.4@4099.23,1964.69 4099.23,2010.76 4108.22,2019.75 4108.22,2270 L2.2@4212.56,2374.34
NetQ1_2: Q1.2 R2.2 | length 213.2
  Top Layer w6: 2699.09,1320 Q1.2@2717.2,1338.11
  Top Layer w30: R2.2@2511.5,1320 2699.09,1320
NetR11_1: R11.1 R12.2 U2.14 | length 438.2
  Top Layer w10: U2.14@4011.64,1851.5 4011.64,1826.3 4022.52,1815.41 4022.52,1726.62 4043.55,1705.59 4179.07,1705.59 4191.29,1693.37 R12.2@4191.29,1659.45 ; R12.2@4191.88,1658.86 R11.1@4284.26,1658.86
Q1_CTRL: Q1.1 R4.2 | length 992.7
  Top Layer w6: Q1.1@2717.2,1351.89 2717.2,1363.71
  Top Layer w20: 2717.2,1363.71 2750,1396.51 2750,2328.64 R4.2@2751.67,2330.31
Q2_CTRL: Q2.1 R5.2 | length 1063.6
  Top Layer w6: Q2.1@3362.2,1356.89 3362.2,1392.6
  Top Layer w20: R5.2@3151.92,2331.79 3150,2329.87 3150,2273.03 3362.2,2060.82 3362.2,1392.6
VBAT: BT1.1 J1.1 J1.2 J2.1 JP1.3 | length 400
  Top Layer w30: JP1.3@1030,1400 J1.1@1030,1600 J1.2@1030,1700 J2.1@1030,1800
VIN: C1.1 C2.1 J4.1 J9.1 JP2.1 JP3.1 JP4.1 JP5.1 JP6.1 JP7.1 JP8.1 JP9.1 U1.1 | length 6232
  Top Layer w10: C2.1@1699.77,1330.9 1699.77,1352.03 1708.16,1360.42 U1.1@1708.16,1393
  Top Layer w20: J4.1@1340,1300 1336.4,1296.4 1336.4,1153.6 ; JP3.1@1500,280 1500,220 1450,170 1045,170 1000,215 JP2.1@1000,280 1000,817.2 1336.4,1153.6 ; J9.1@1500,800 1500,990 1336.4,1153.6 ; v4@1577.91,1422.91 v4(1585,1430)
  Bottom Layer w20: JP5.1@1450,2650 1450,2735 ; v4(1585,1430) 1585,2055 1050,2590 JP4.1@1050,2650 1050,2700 1085,2735 1450,2735 ; JP6.1@1850,2650 1850,2733.4 1851.6,2735 1450,2735 ; 1855,2735 2252.5,2735 ; JP7.1@2250,2650 2250,2732.5 2252.5,2735 ; JP7.1@2253.3,2636.5 JP7.1@2253.3,2666.7 ; JP8.1@2650,2650 2650,2735 ; JP9.1@3050,2650 2965,2735 2650,2735 ; 2252.5,2735 2650,2735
